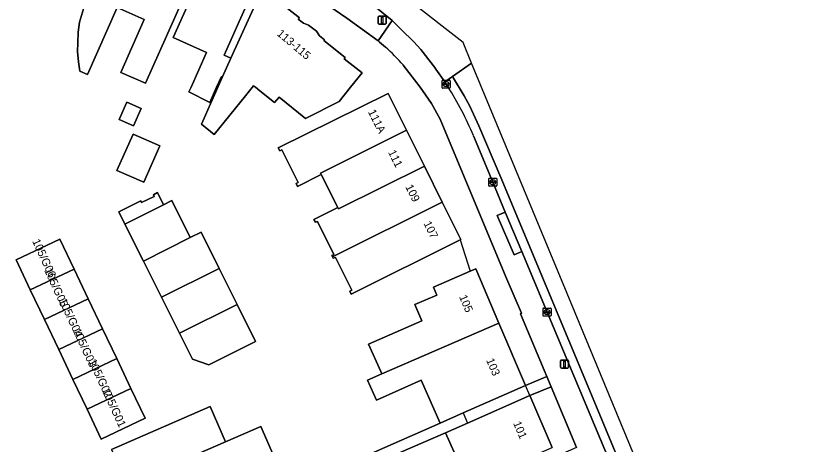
# Model space of a CAD drawing. Extents: x 159371 to 159986, y 382987 to 383597.
# Drawn here: x 159840 to 159940.1, y 383455.5 to 383508.8 of the extents above; entities that cross this region are included whole.
import ezdxf

# ---------------------------------------------------------------- set-up
doc = ezdxf.new("R2010")
doc.units = 0
for name, color, linetype in [('IMGEO_Erf', 7, 'Continuous'), ('IMGEO_Hek', 7, 'Continuous'), ('IMGEO_Kolk', 7, 'Continuous'), ('IMGEO_Lichtmast', 7, 'Continuous'), ('IMGEO_Pand', 7, 'Continuous'), ('IMGEO_Pand_nummerreeks', 7, 'Continuous'), ('IMGEO_Pand_overbouw', 7, 'Continuous'), ('IMGEO_Rijbaan_lokaal_gesloten', 7, 'Continuous'), ('IMGEO_Rijbaan_lokaal_open', 7, 'Continuous'), ('IMGEO_Voetpad_open', 7, 'Continuous')]:
    doc.layers.add(name, color=color, linetype=linetype)

msp = doc.modelspace()

# ---------------------------------------------------------------- linework, layer by layer
at = {"layer": 'IMGEO_Erf'}
for points in [[(159861.41, 383512.57), (159856.03, 383500.47), (159852.95, 383501.83), (159855.88, 383508.42), (159852.52, 383509.91), (159848.81, 383501.57), (159847.88, 383501.98), (159847.69, 383503.13), (159847.58, 383504.41), (159847.61, 383505.52), (159847.66, 383506.82), (159847.85, 383508.05), (159848.34, 383509.71)], [(159869.73, 383512.85), (159865.79, 383503.96), (159866.62, 383503.59), (159870.04, 383511.16)], [(159870.77, 383512.07), (159875.13, 383508.62), (159874.99, 383508.44), (159875.63, 383507.94), (159876.25, 383507.71), (159877.26, 383506.94), (159877.63, 383506.36), (159878.24, 383505.86), (159878.18, 383505.78), (159880.83, 383503.68), (159880.69, 383503.51), (159882.9, 383501.79), (159881.48, 383500), (159880.06, 383498.2), (159875.9, 383496.1), (159872.6, 383498.76), (159872.05, 383498.07), (159870.23, 383499.53), (159869.69, 383499.97), (159869.44, 383500.17), (159868.43, 383498.92), (159864.57, 383494.12), (159862.97, 383495.41), (159865.56, 383501.21), (159865.44, 383501.31), (159864.86, 383500), (159864, 383498.09), (159861.41, 383499.41), (159861.68, 383500), (159863.6, 383504.31), (159859.46, 383506.15), (159862.09, 383512.08)], [(159885.83, 383504.98), (159885.09, 383505.59), (159884.89, 383505.74), (159881.02, 383508.56), (159876.55, 383511.66)], [(159879.9, 383452.66), (159892.59, 383458.24), (159890.25, 383463.57), (159884.68, 383461.11), (159883.59, 383463.59), (159885.35, 383464.36), (159885.22, 383464.64), (159883.72, 383468.05), (159890.33, 383470.96), (159889.45, 383472.97), (159892.2, 383474.15), (159891.76, 383475.15), (159896.32, 383477.11), (159897.01, 383477.41), (159899.89, 383470.68), (159903.2, 383462.92), (159905.84, 383464.02), (159902.59, 383471.81), (159902.68, 383471.89), (159900.77, 383476.42), (159892.59, 383496), (159891.51, 383497.97), (159890.78, 383499.02), (159890.13, 383500), (159888.03, 383502.73)], [(159909.54, 383455.19), (159906.37, 383462.76), (159903.74, 383461.66), (159906.49, 383455.22)], [(159851.82, 383454.95), (159864.06, 383460.3), (159865.97, 383455.93), (159870.35, 383457.84), (159884.54, 383425.4)], [(159895.03, 383453.04), (159893.27, 383457.04), (159883.41, 383452.76)]]:
    msp.add_lwpolyline(points, dxfattribs=at)
for points in [[(159872.69, 383492.09), (159872.51, 383492.45), (159886.14, 383499.22), (159888.42, 383494.64), (159890.65, 383490.16), (159892.87, 383485.68), (159895.17, 383481.05), (159895.07, 383481), (159881.54, 383474.28), (159881.37, 383474.64), (159881.62, 383474.76), (159879.6, 383478.83), (159879.34, 383478.72), (159879.25, 383478.91), (159879.17, 383479.08), (159879.42, 383479.21), (159877.37, 383483.28), (159877.12, 383483.2), (159876.94, 383483.55), (159879.89, 383485.03), (159877.83, 383489.13), (159874.89, 383487.65), (159874.71, 383488.02), (159874.97, 383488.14), (159872.95, 383492.21)], [(159853.71, 383498.13), (159855.5, 383497.33), (159854.55, 383495.18), (159852.75, 383495.98)], [(159854.48, 383494.16), (159857.81, 383492.69), (159855.8, 383488.17), (159852.47, 383489.65)], [(159853.48, 383482.98), (159852.73, 383484.49), (159855.45, 383485.85), (159855.55, 383485.64), (159857.1, 383486.41), (159857, 383486.62), (159857.52, 383486.88), (159858.27, 383485.37), (159859.31, 383485.89), (159861.59, 383481.32), (159862.93, 383481.98), (159865.18, 383477.47), (159867.4, 383473), (159869.7, 383468.39), (159863.9, 383465.5), (159861.86, 383466.17), (159860.24, 383469.43), (159858.01, 383473.9), (159855.78, 383478.37)], [(159843.49, 383471.1), (159841.73, 383474.81), (159839.97, 383478.52), (159845.41, 383481.1), (159847.17, 383477.39), (159848.93, 383473.68), (159850.69, 383469.97), (159852.45, 383466.26), (159854.21, 383462.55), (159855.98, 383458.84), (159850.54, 383456.26), (159848.78, 383459.97), (159847.02, 383463.68), (159845.25, 383467.39)]]:
    msp.add_lwpolyline(points, close=True, dxfattribs=at)
msp.add_arc((159853.37, 383470.95), 47.03, 42.5149, 46.3531, dxfattribs=at)
at = {"layer": 'IMGEO_Hek'}
msp.add_lwpolyline([(159895.07, 383481), (159896.32, 383477.11)], dxfattribs=at)
at = {"layer": 'IMGEO_Kolk'}
for p, q in [((159892.84, 383499.94), (159892.84, 383500.79)), ((159892.91, 383500.87), (159893.76, 383500.87)), ((159893.32, 383500.65), (159893.35, 383500.65)), ((159893.84, 383500.79), (159893.84, 383499.94)), ((159893.76, 383499.87), (159892.91, 383499.87)), ((159893.09, 383500.36), (159893.09, 383500.37)), ((159893.53, 383500.32), (159893.13, 383500.32)), ((159893.14, 383500.41), (159893.54, 383500.41)), ((159893.35, 383500.09), (159893.32, 383500.09)), ((159893.58, 383500.37), (159893.58, 383500.36)), ((159898.63, 383487.75), (159898.63, 383488.61)), ((159898.7, 383488.68), (159899.55, 383488.68)), ((159899.63, 383488.61), (159899.63, 383487.75)), ((159899.55, 383487.68), (159898.7, 383487.68)), ((159898.89, 383488.17), (159898.89, 383488.19)), ((159898.93, 383488.22), (159899.33, 383488.22)), ((159899.32, 383488.14), (159898.93, 383488.14)), ((159899.14, 383487.9), (159899.11, 383487.9)), ((159899.12, 383488.46), (159899.14, 383488.46)), ((159899.37, 383488.19), (159899.37, 383488.17)), ((159905.44, 383472.54), (159906.29, 383472.54)), ((159905.37, 383471.61), (159905.37, 383472.47)), ((159906.29, 383471.54), (159905.44, 383471.54)), ((159905.62, 383472.03), (159905.62, 383472.05)), ((159906.06, 383472), (159905.66, 383472)), ((159905.67, 383472.08), (159906.06, 383472.08)), ((159905.85, 383472.32), (159905.88, 383472.32)), ((159905.88, 383471.76), (159905.85, 383471.76)), ((159906.11, 383472.05), (159906.11, 383472.03)), ((159906.37, 383472.47), (159906.37, 383471.61))]:
    msp.add_line(p, q, dxfattribs=at)
for points in [[(159892.84, 383499.94), (159892.84, 383500.79)], [(159892.91, 383500.87), (159893.76, 383500.87)], [(159893.84, 383500.79), (159893.84, 383499.94)], [(159893.76, 383499.87), (159892.91, 383499.87)], [(159898.63, 383487.75), (159898.63, 383488.61)], [(159898.7, 383488.68), (159899.55, 383488.68)], [(159899.63, 383488.61), (159899.63, 383487.75)], [(159899.55, 383487.68), (159898.7, 383487.68)], [(159905.44, 383472.54), (159906.29, 383472.54)], [(159905.37, 383471.61), (159905.37, 383472.47)], [(159906.29, 383471.54), (159905.44, 383471.54)], [(159906.37, 383472.47), (159906.37, 383471.61)]]:
    msp.add_lwpolyline(points, dxfattribs=at)
for centre, radius, start, end in [((159892.91, 383500.79), 0.0765, 91.552, 178.448), ((159892.91, 383500.79), 0.0765, 91.552, 178.448), ((159893.76, 383500.79), 0.0765, 1.552, 88.448), ((159893.76, 383500.79), 0.0765, 1.552, 88.448), ((159892.91, 383499.94), 0.0765, 181.552, 268.448), ((159892.91, 383499.94), 0.0765, 181.552, 268.448), ((159893.14, 383500.37), 0.0403, 85.8775, 175.7526), ((159893.13, 383500.36), 0.0366, 178.938, 274.7102), ((159893.54, 383500.37), 0.043, 264.8664, 352.4533), ((159893.54, 383500.37), 0.0386, 1.7309, 96.639), ((159893.76, 383499.94), 0.0765, 271.552, 358.448), ((159893.76, 383499.94), 0.0765, 271.552, 358.448), ((159898.7, 383488.6), 0.0765, 91.552, 178.448), ((159898.7, 383488.6), 0.0765, 91.552, 178.448), ((159899.55, 383488.6), 0.0765, 1.552, 88.448), ((159899.55, 383488.6), 0.0765, 1.552, 88.448), ((159898.7, 383487.76), 0.0765, 181.552, 268.448), ((159898.7, 383487.76), 0.0765, 181.552, 268.448), ((159898.93, 383488.18), 0.0403, 85.8775, 175.7526), ((159898.92, 383488.17), 0.0366, 178.938, 274.7102), ((159899.33, 383488.18), 0.043, 264.8664, 352.4533), ((159899.33, 383488.18), 0.0386, 1.7309, 96.639), ((159899.55, 383487.76), 0.0765, 271.552, 358.448), ((159899.55, 383487.76), 0.0765, 271.552, 358.448), ((159905.44, 383472.46), 0.0765, 91.552, 178.448), ((159905.44, 383472.46), 0.0765, 91.552, 178.448), ((159906.29, 383472.46), 0.0765, 1.552, 88.448), ((159906.29, 383472.46), 0.0765, 1.552, 88.448), ((159905.44, 383471.62), 0.0765, 181.552, 268.448), ((159905.44, 383471.62), 0.0765, 181.552, 268.448), ((159905.66, 383472.04), 0.0403, 85.8775, 175.7526), ((159905.66, 383472.03), 0.0366, 178.938, 274.7102), ((159906.07, 383472.04), 0.0386, 1.7309, 96.639), ((159906.07, 383472.04), 0.043, 264.8664, 352.4533), ((159906.29, 383471.62), 0.0765, 271.552, 358.448), ((159906.29, 383471.62), 0.0765, 271.552, 358.448)]:
    msp.add_arc(centre, radius, start, end, dxfattribs=at)
for centre, major_axis, ratio, start_param, end_param in [((159893.32, 383500.37), (-0.387, 0.002), 0.722429, 4.712389, 7.853982), ((159893.35, 383500.37), (-0.39, 0.002), 0.717154, 1.570796, 4.712389), ((159899.11, 383488.18), (-0.387, 0.002), 0.722429, 4.712389, 7.853982), ((159899.14, 383488.18), (-0.39, 0.002), 0.717154, 1.570796, 4.712389), ((159905.85, 383472.04), (-0.387, 0.002), 0.722429, 4.712389, 7.853982), ((159905.88, 383472.04), (-0.39, 0.002), 0.717154, 1.570796, 4.712389)]:
    msp.add_ellipse(centre, major_axis=major_axis, ratio=ratio, start_param=start_param, end_param=end_param, dxfattribs=at)
at = {"layer": 'IMGEO_Lichtmast'}
for p, q in [((159884.9, 383507.92), (159884.9, 383508.72)), ((159884.9, 383508.72), (159884.9, 383507.92)), ((159885, 383508.82), (159885.79, 383508.82)), ((159885.79, 383508.82), (159885, 383508.82)), ((159885.89, 383508.72), (159885.89, 383507.92)), ((159885.89, 383507.92), (159885.89, 383508.72)), ((159885.79, 383507.82), (159885, 383507.82)), ((159885, 383507.82), (159885.79, 383507.82)), ((159907.55, 383465.18), (159907.55, 383465.98)), ((159907.55, 383465.98), (159907.55, 383465.18)), ((159907.65, 383466.08), (159908.44, 383466.08)), ((159908.44, 383466.08), (159907.65, 383466.08)), ((159908.54, 383465.98), (159908.54, 383465.18)), ((159908.54, 383465.18), (159908.54, 383465.98)), ((159908.44, 383465.08), (159907.65, 383465.08)), ((159907.65, 383465.08), (159908.44, 383465.08))]:
    msp.add_line(p, q, dxfattribs=at)
for points in [[(159885.32, 383508.7), (159885.47, 383508.7), (159885.47, 383507.95), (159885.32, 383507.95), (159885.32, 383508.7)], [(159907.97, 383465.95), (159908.12, 383465.95), (159908.12, 383465.2), (159907.97, 383465.2), (159907.97, 383465.95)]]:
    msp.add_lwpolyline(points, dxfattribs=at)
for centre, start, end in [((159885, 383508.72), 90, 180), ((159885, 383508.72), 90, 180), ((159885.79, 383508.72), 0, 90), ((159885.79, 383508.72), 360, 90), ((159885, 383507.92), 180, 270), ((159885, 383507.92), 180, 270), ((159885.79, 383507.92), 270, 0), ((159885.79, 383507.92), 270, 0), ((159907.65, 383465.98), 90, 180), ((159907.65, 383465.98), 90, 180), ((159908.44, 383465.98), 0, 90), ((159908.44, 383465.98), 360, 90), ((159907.65, 383465.18), 180, 270), ((159907.65, 383465.18), 180, 270), ((159908.44, 383465.18), 270, 0), ((159908.44, 383465.18), 270, 0)]:
    msp.add_arc(centre, 0.1, start, end, dxfattribs=at)
at = {"layer": 'IMGEO_Pand'}
for points in [[(159854.58, 383516.78), (159856.46, 383521.41), (159850.67, 383523.77), (159850.57, 383523.52), (159847.66, 383524.71), (159845.78, 383520.08), (159844.41, 383516.72), (159847.4, 383515.51), (159846.32, 383512.84), (159848.64, 383511.89), (159849.14, 383511.68), (159848.34, 383509.71), (159847.85, 383508.05), (159847.66, 383506.82), (159847.61, 383505.52), (159847.58, 383504.41), (159847.69, 383503.13), (159847.88, 383501.98), (159848.81, 383501.57), (159852.52, 383509.91), (159853.4, 383511.91), (159852.72, 383512.21)], [(159852.52, 383509.91), (159855.88, 383508.42), (159852.95, 383501.83), (159856.03, 383500.47), (159861.41, 383512.57), (159863.44, 383517.14), (159857.35, 383520.78), (159855.32, 383516.21), (159853.4, 383511.91)], [(159865.56, 383501.21), (159866.62, 383503.59), (159865.79, 383503.96), (159869.73, 383512.85), (159867.78, 383514.03), (159867.89, 383514.27), (159864.12, 383516.64), (159862.09, 383512.08), (159859.46, 383506.15), (159863.6, 383504.31), (159861.68, 383500), (159861.41, 383499.41), (159864, 383498.09), (159864.86, 383500), (159865.44, 383501.31)], [(159877.83, 383489.13), (159877.74, 383489.32), (159888.42, 383494.64), (159886.14, 383499.22), (159872.51, 383492.45), (159872.69, 383492.09), (159872.95, 383492.21), (159874.97, 383488.14), (159874.71, 383488.02), (159874.89, 383487.65)], [(159852.75, 383495.98), (159854.55, 383495.18), (159855.5, 383497.33), (159853.71, 383498.13)], [(159890.65, 383490.16), (159888.42, 383494.64), (159877.74, 383489.32), (159877.83, 383489.13), (159879.89, 383485.03), (159879.98, 383484.85)], [(159852.47, 383489.65), (159855.8, 383488.17), (159857.81, 383492.69), (159854.48, 383494.16)], [(159890.65, 383490.16), (159879.98, 383484.85), (159879.89, 383485.03), (159876.94, 383483.55), (159877.12, 383483.2), (159877.37, 383483.28), (159879.42, 383479.21), (159879.17, 383479.08), (159879.25, 383478.91), (159892.87, 383485.68)], [(159858.27, 383485.37), (159857.52, 383486.88), (159857, 383486.62), (159857.1, 383486.41), (159855.55, 383485.64), (159855.45, 383485.85), (159852.73, 383484.49), (159853.48, 383482.98)], [(159859.31, 383485.89), (159858.27, 383485.37), (159853.48, 383482.98), (159855.78, 383478.37), (159861.59, 383481.32)], [(159892.87, 383485.68), (159879.25, 383478.91), (159879.34, 383478.72), (159879.6, 383478.83), (159881.62, 383474.76), (159881.37, 383474.64), (159881.54, 383474.28), (159895.07, 383481), (159895.17, 383481.05)], [(159861.59, 383481.32), (159855.78, 383478.37), (159858.01, 383473.9), (159865.18, 383477.47), (159862.93, 383481.98)], [(159847.17, 383477.39), (159845.41, 383481.1), (159839.97, 383478.52), (159841.73, 383474.81)], [(159847.17, 383477.39), (159841.73, 383474.81), (159843.49, 383471.1), (159848.93, 383473.68)], [(159865.18, 383477.47), (159858.01, 383473.9), (159860.24, 383469.43), (159867.4, 383473)], [(159899.89, 383470.68), (159897.01, 383477.41), (159896.32, 383477.11), (159891.76, 383475.15), (159892.2, 383474.15), (159889.45, 383472.97), (159890.33, 383470.96), (159883.72, 383468.05), (159885.22, 383464.64), (159885.35, 383464.36)], [(159843.49, 383471.1), (159845.25, 383467.39), (159850.69, 383469.97), (159848.93, 383473.68)], [(159867.4, 383473), (159860.24, 383469.43), (159861.86, 383466.17), (159863.9, 383465.5), (159869.7, 383468.39)], [(159903.2, 383462.92), (159899.89, 383470.68), (159885.35, 383464.36), (159883.59, 383463.59), (159884.68, 383461.11), (159890.25, 383463.57), (159892.59, 383458.24), (159895.46, 383459.51)], [(159847.02, 383463.68), (159852.45, 383466.26), (159850.69, 383469.97), (159845.25, 383467.39)], [(159854.21, 383462.55), (159852.45, 383466.26), (159847.02, 383463.68), (159848.78, 383459.97)], [(159854.21, 383462.55), (159848.78, 383459.97), (159850.54, 383456.26), (159855.98, 383458.84)], [(159895.03, 383453.04), (159892.82, 383452.07), (159893.81, 383449.82), (159893.88, 383449.66), (159906.49, 383455.22), (159903.74, 383461.66), (159896.01, 383458.25), (159893.27, 383457.04)], [(159865.97, 383455.93), (159864.06, 383460.3), (159851.82, 383454.95), (159852.29, 383453.89), (159853.65, 383450.77), (159853.74, 383450.61)], [(159870.35, 383457.84), (159865.97, 383455.93), (159853.74, 383450.61), (159861.78, 383436.02), (159869.33, 383418.75), (159884.54, 383425.4)]]:
    msp.add_lwpolyline(points, close=True, dxfattribs=at)
msp.add_lwpolyline([(159870.04, 383511.16), (159866.62, 383503.59), (159865.56, 383501.21), (159862.97, 383495.41), (159864.57, 383494.12), (159868.43, 383498.92), (159869.44, 383500.17), (159869.69, 383499.97), (159870.23, 383499.53), (159872.05, 383498.07), (159872.6, 383498.76), (159875.9, 383496.1), (159880.06, 383498.2), (159881.48, 383500), (159882.9, 383501.79), (159880.69, 383503.51), (159880.83, 383503.68), (159878.18, 383505.78), (159878.24, 383505.86), (159877.63, 383506.36), (159877.26, 383506.94), (159876.25, 383507.71), (159875.63, 383507.94), (159874.99, 383508.44), (159875.13, 383508.62), (159870.77, 383512.07)], dxfattribs=at)
at = {"layer": 'IMGEO_Pand_overbouw'}
msp.add_lwpolyline([(159903.2, 383462.92), (159895.46, 383459.51), (159896.01, 383458.25), (159903.74, 383461.66)], close=True, dxfattribs=at)
at = {"layer": 'IMGEO_Rijbaan_lokaal_gesloten'}
for points in [[(159938.37, 383396.95), (159930.55, 383415.74), (159918.9, 383443.6), (159911.4, 383461.75), (159900.13, 383488.78), (159897.4, 383495.18), (159896.28, 383497.63), (159895.58, 383498.93), (159894.12, 383501.31), (159893.17, 383500.65), (159893.34, 383500.37), (159893.46, 383500.19), (159893.59, 383500)], [(159896.74, 383493.96), (159899.13, 383488.18), (159900.68, 383484.46), (159902.73, 383479.55), (159905.87, 383472.04), (159913.8, 383453.14), (159914.14, 383452.31), (159917.54, 383444.12), (159918.13, 383442.72), (159922.86, 383431.38), (159925.95, 383423.98), (159926.39, 383422.95), (159928.13, 383418.79), (159930.66, 383412.74), (159937.38, 383396.59)]]:
    msp.add_lwpolyline(points, dxfattribs=at)
msp.add_arc((159859.89, 383478.59), 39.92, 22.653, 32.4345, dxfattribs=at)
at = {"layer": 'IMGEO_Rijbaan_lokaal_open'}
msp.add_lwpolyline([(159880.93, 383512.92), (159882.81, 383511.42), (159886.66, 383508.29), (159887.78, 383507.16), (159889.34, 383505.63), (159890.22, 383504.66), (159891.79, 383502.66), (159891.93, 383502.43), (159892.08, 383502.22), (159893.17, 383500.65), (159894.12, 383501.31), (159896.51, 383502.97), (159895.44, 383505.55), (159888.94, 383510.65), (159885.39, 383513.1), (159870.06, 383523.69), (159848.63, 383532.73), (159843.9, 383534.72)], dxfattribs=at)
msp.add_lwpolyline([(159896.51, 383502.97), (159894.12, 383501.31), (159895.58, 383498.93), (159896.28, 383497.63), (159897.4, 383495.18), (159900.13, 383488.78), (159911.4, 383461.75), (159918.9, 383443.6), (159930.55, 383415.74), (159938.37, 383396.95), (159940.11, 383397.58), (159940.11, 383397.58), (159908.35, 383474.34)], close=True, dxfattribs=at)
at = {"layer": 'IMGEO_Voetpad_open'}
for points in [[(159876.55, 383511.66), (159881.02, 383508.56), (159884.89, 383505.74), (159886.66, 383508.29), (159882.81, 383511.42)], [(159893.59, 383500), (159893.46, 383500.19), (159893.34, 383500.37), (159893.17, 383500.65), (159892.08, 383502.22), (159891.93, 383502.43), (159891.79, 383502.66), (159890.22, 383504.66), (159889.34, 383505.63), (159887.78, 383507.16), (159886.66, 383508.29), (159884.89, 383505.74), (159885.09, 383505.59), (159885.83, 383504.98)], [(159888.03, 383502.73), (159890.13, 383500), (159890.78, 383499.02), (159891.51, 383497.97), (159892.59, 383496), (159900.77, 383476.42), (159902.68, 383471.89), (159902.59, 383471.81), (159905.84, 383464.02), (159906.37, 383462.76), (159909.54, 383455.19), (159907.44, 383454.3), (159914.09, 383438.32), (159914.22, 383438.01), (159913.9, 383437.89), (159914.24, 383436.94), (159917.09, 383430.31), (159919.22, 383425.33), (159921.18, 383420.77), (159923.14, 383416.2), (159923.47, 383415.42), (159926.6, 383416.76), (159929.67, 383409.62), (159932.94, 383401.98)], [(159913.18, 383451.91), (159914.14, 383452.31), (159913.8, 383453.14), (159905.87, 383472.04), (159902.73, 383479.55), (159901.78, 383479.15), (159899.69, 383484.04), (159900.68, 383484.46), (159899.13, 383488.18), (159896.74, 383493.96)]]:
    msp.add_lwpolyline(points, dxfattribs=at)
for points in [[(159900.68, 383484.46), (159899.69, 383484.04), (159901.78, 383479.15), (159902.73, 383479.55)], [(159893.27, 383457.04), (159896.01, 383458.25), (159903.74, 383461.66), (159906.37, 383462.76), (159905.84, 383464.02), (159903.2, 383462.92), (159895.46, 383459.51), (159892.59, 383458.24), (159879.9, 383452.66), (159880.54, 383451.35), (159883.41, 383452.76)]]:
    msp.add_lwpolyline(points, close=True, dxfattribs=at)
for centre, radius, start, end in [((159853.37, 383470.95), 47.03, 42.5149, 46.3531), ((159859.89, 383478.59), 39.92, 22.653, 32.4345)]:
    msp.add_arc(centre, radius, start, end, dxfattribs=at)

# ---------------------------------------------------------------- texts
at = {"layer": 'IMGEO_Pand_nummerreeks'}
for s, rotation, p in [('113-115', 319.7096, (159872.26, 383506.51)), ('111A', 296.4173, (159883.62, 383496.93)), ('111', 296.4173, (159886.11, 383491.91)), ('109', 296.4173, (159888.25, 383487.61)), ('107', 296.4173, (159890.51, 383483.06)), ('105/G06', 294.6582, (159841.94, 383480.86)), ('105/G05', 294.6582, (159843.43, 383477.23)), ('105/G04', 294.6582, (159845.25, 383473.48)), ('105', 293.1186, (159894.93, 383473.94)), ('105/G03', 294.6582, (159846.99, 383469.74)), ('105/G02', 294.6582, (159848.93, 383465.94)), ('103', 293.1186, (159898.29, 383466.06)), ('105/G01', 294.6582, (159850.62, 383462.27)), ('101', 293.12, (159901.64, 383458.23))]:
    msp.add_text(s, height=1, rotation=rotation, dxfattribs=at).set_placement(p)

doc.saveas('drawing.dxf')
